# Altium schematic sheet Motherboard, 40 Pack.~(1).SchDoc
size A
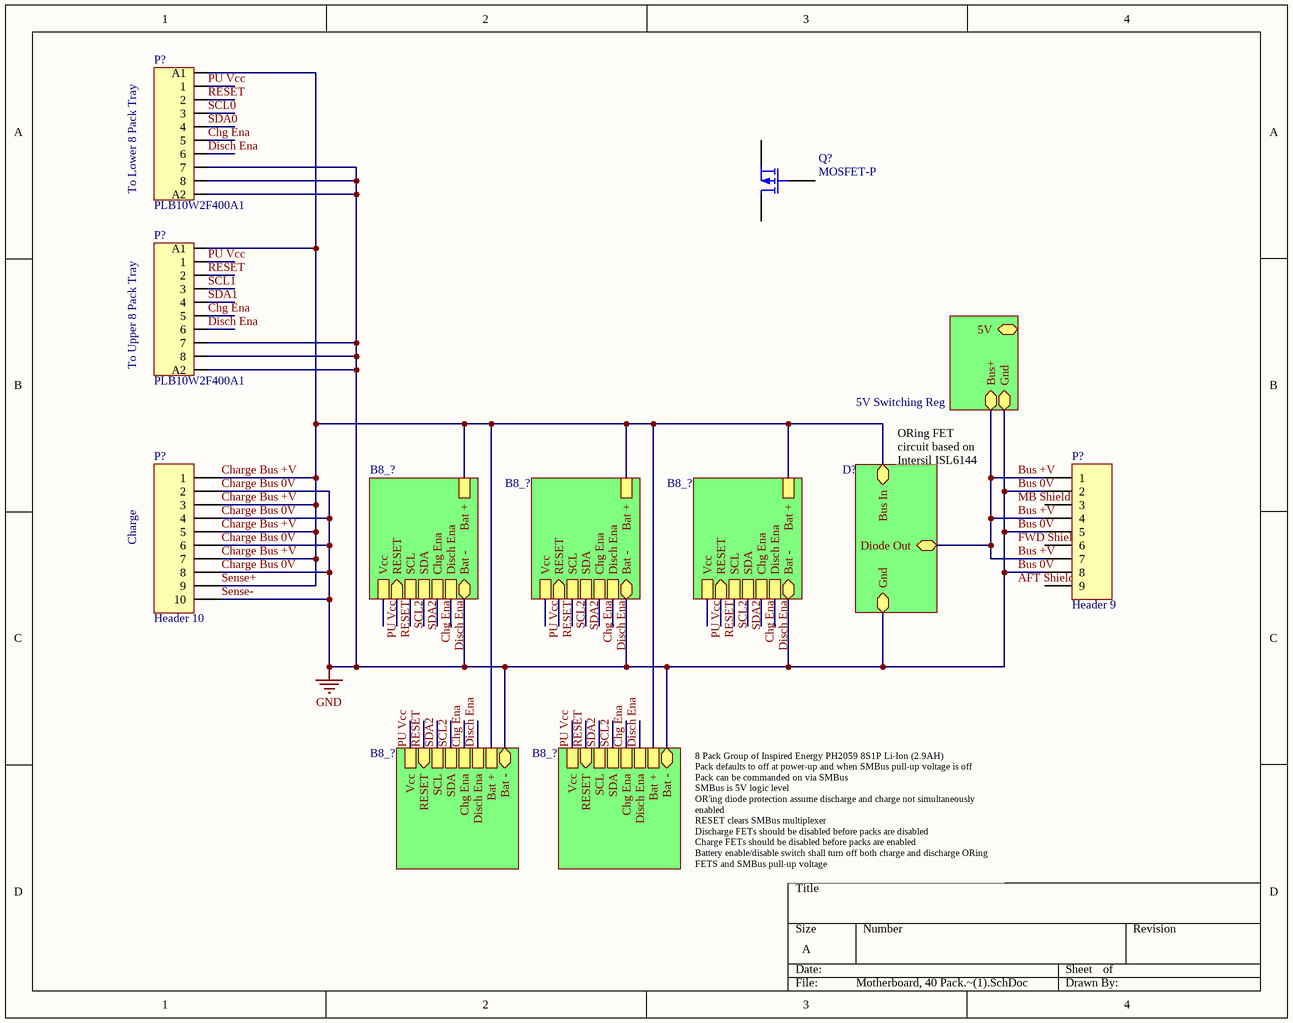
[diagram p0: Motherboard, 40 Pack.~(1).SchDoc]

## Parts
(Parts that share a designator on the sheet are numbered #1, #2 ... from top to bottom, then left to right.)
P?#1  PLB10W2F400A1
P?#2  PLB10W2F400A1
P?#3  Header 10  [HDR1X10]
P?#4  Header 9  [HDR1X9]
Q?  MOSFET-P  [BCY-W3/B.8]

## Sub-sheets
5V Switching Reg = File Name: Bus+, Gnd, 5V
B8_? = 8 Pack Controller.SchDoc: Bat +, Disch Ena, Chg Ena, Vcc, SDA, SCL, RESET (in), Bat - (bidir)
B8_? = 8 Pack Controller.SchDoc: Bat +, Disch Ena, Chg Ena, Vcc, SDA, SCL, RESET (in), Bat - (bidir)
B8_? = 8 Pack Controller.SchDoc: Bat +, Disch Ena, Chg Ena, Vcc, SDA, SCL, RESET (in), Bat - (bidir)
B8_? = 8 Pack Controller.SchDoc: Bat +, Disch Ena, Chg Ena, Vcc, SDA, SCL, RESET (in), Bat - (bidir)
B8_? = 8 Pack Controller.SchDoc: Bat +, Disch Ena, Chg Ena, Vcc, SDA, SCL, RESET (in), Bat - (bidir)
D? = File Name: Bus In, Diode Out, Gnd

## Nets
Bus 0V: P?#1.7 P?#1.8 P?#1.A2 P?#2.7 P?#2.8 P?#2.A2 P?#3.2 P?#3.4 P?#3.6 P?#3.8 P?#3.10 P?#4.2 P?#4.5 P?#4.8 ; sheet B8_?/Bat -, sheet B8_?/Bat -, sheet B8_?/Bat -, sheet B8_?/Bat -, sheet B8_?/Bat -, sheet D?/Gnd, sheet 5V Switching Reg/Gnd  [also labelled Charge Bus 0V, GND, Sense-]
Bus +V: P?#4.1 P?#4.4 P?#4.7 ; sheet D?/Diode Out, sheet 5V Switching Reg/Bus+
Charge Bus +V: P?#1.A1 P?#2.A1 P?#3.1 P?#3.3 P?#3.5 P?#3.7 P?#3.9 ; sheet B8_?/Bat +, sheet B8_?/Bat +, sheet B8_?/Bat +, sheet B8_?/Bat +, sheet B8_?/Bat +, sheet D?/Bus In  [also labelled Sense+]
Chg Ena: P?#1.5 P?#2.5 ; sheet B8_?/Chg Ena, sheet B8_?/Chg Ena, sheet B8_?/Chg Ena, sheet B8_?/Chg Ena, sheet B8_?/Chg Ena
Disch Ena: P?#1.6 P?#2.6 ; sheet B8_?/Disch Ena, sheet B8_?/Disch Ena, sheet B8_?/Disch Ena, sheet B8_?/Disch Ena, sheet B8_?/Disch Ena
PU Vcc: P?#1.1 P?#2.1 ; sheet B8_?/Vcc, sheet B8_?/Vcc, sheet B8_?/Vcc, sheet B8_?/Vcc, sheet B8_?/Vcc
RESET: P?#1.2 P?#2.2 ; sheet B8_?/RESET, sheet B8_?/RESET, sheet B8_?/RESET, sheet B8_?/RESET, sheet B8_?/RESET
SCL0: P?#1.3
SCL1: P?#2.3
SCL2: sheet B8_?/SCL, sheet B8_?/SCL, sheet B8_?/SCL, sheet B8_?/SDA, sheet B8_?/SDA
SDA0: P?#1.4
SDA1: P?#2.4
SDA2: sheet B8_?/SDA, sheet B8_?/SDA, sheet B8_?/SDA, sheet B8_?/SCL, sheet B8_?/SCL

Not connected (* = marked no-connect by the designer): P?#4 3 6 9; Q? 1(D) 2(G) 3(S)

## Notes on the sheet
- To Lower 8 Pack Tray
- To Upper 8 Pack Tray
- ORing FET circuit based on Intersil ISL6144
- Charge
- 8 Pack Group of Inspired Energy PH2059 8S1P Li-Ion (2.9AH)
  Pack defaults to off at power-up and when SMBus pull-up voltage is off
  Pack can be commanded on via SMBus
  SMBus is 5V logic level
  OR'ing diode protection assume discharge and charge not simultaneously enabled
  RESET clears SMBus multiplexer
  Discharge FETs should be disabled before packs are disabled
  Charge FETs should be disabled before packs are enabled
  Battery enable/disable switch shall turn off both charge and discharge ORing FETS and SMBus pull-up voltage
- Labels drawn without touching a wire or pin: AFT Shield, FWD Shield, MB Shield

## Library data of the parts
P?#3 = Header 10: Header, 10-Pin
P?#4 = Header 9: Header, 9-Pin
Q? = MOSFET-P: P-Channel MOSFET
